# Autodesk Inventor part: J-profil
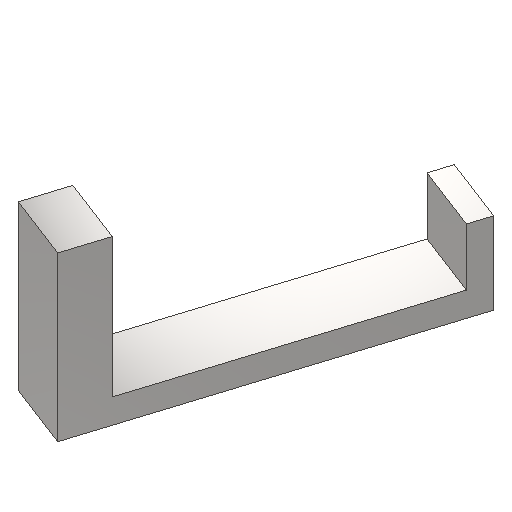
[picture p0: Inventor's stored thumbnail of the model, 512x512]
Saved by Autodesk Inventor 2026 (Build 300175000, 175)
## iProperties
Created: 2004-09
Part Number: J-profil
Document SubType Name: Modeling
Designer: Lars Bertram Pedersen
Manufacturer: Standard
Standards Organization: Custom
Material: Steel, Mild
Density: 7.85 g/cm^3
Appearance: Semi-Polished
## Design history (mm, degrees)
sketch "Sketch1"
  geometry: L1 (-44.965, -4.227)-(35.035, -4.227); L2 (35.035, -4.227)-(35.035, 15.773); L3 (35.035, 15.773)-(30.035, 15.773); L4 (30.035, 15.773)-(30.035, 1.773); L5 (30.035, 1.773)-(-34.965, 1.773); L6 (-34.965, 1.773)-(-34.965, 35.773); L7 (-34.965, 35.773)-(-44.965, 35.773); L8 (-44.965, 35.773)-(-44.965, -4.227)
  constraints: 16 end point, 5 perpendicular, 2 parallel, 1 horizontal
  dimensions: "d1" = 5 distance between parallel lines of L2 L4; "d3" = 80 distance of L1.start L1.end; "d4" = 14 distance between parallel lines of L3 L5; "d6" = 6 distance between parallel lines of L1 L5; "d7" = 10 distance of L6.end L7.end; "d8" = 40 distance of L7.end L1.start
extrude "Extrusion1" new body sketch "Sketch1" distance "d9" = 15; taper "d10" = 0 deg
body "Solid1"
